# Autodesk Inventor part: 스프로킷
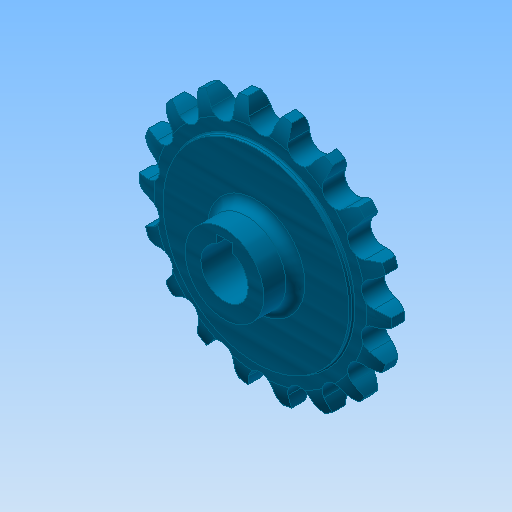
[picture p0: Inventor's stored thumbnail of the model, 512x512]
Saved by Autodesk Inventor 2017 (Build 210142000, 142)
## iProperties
Created: 2016-03
Part Number: 스프로킷
Material: 강철, 탄소
Document SubType Name: Modeling
Designer: mduedu
Density: 7.87 g/cm^3
Mass: 301.818 g
Surface Area: 124.882 cm^2
Volume: 38.3505 cm^3
Appearance: 하늘색 중간
Author: mduedu
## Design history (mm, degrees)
sketch "스케치1"
  geometry: L1 (0, 5)-(29.5, 5); L2 (29.5, 5)-(29.5, 4.1); L3 (30, 3.6)-(33.625, 3.6); L4 (40, 2)-(40, 0); L5 (40, 0)-(0, 0); L6 (0, 0)-(0, 5); L7 (0, -5)-(29.5, -5); L8 (29.5, -5)-(29.5, -4.1); L9 (30, -3.6)-(33.625, -3.6); L10 (40, -2)-(40, 0); L11 (0, 0)-(0, -5); A1 r 13.5 centre (33.625, -9.9) between (40, 2) and (33.625, 3.6); A2 r 13.5 centre (33.625, 9.9) between (33.625, -3.6) and (40, -2); A3 r 0.5 centre (30, 4.1) between (29.5, 4.1) and (30, 3.6); A4 r 0.5 centre (30, -4.1) between (30, -3.6) and (29.5, -4.1); 2 further points
  constraints: 22 end point, 8 point on circle, 6 symmetric about line, 5 tangent, 4 centre point, 4 parallel, 4 point on line, 1 equal radius, 1 horizontal, 1 perpendicular, 1 other
  dimensions: "d0" = 80 diameter of L4 L6; "d2" = 59 diameter of L2 L6; "d3" = 1.6 vertical distance of L4.start L3.end; "d4" = 3.6 distance from line of L4.end L3; "d5" = 5 distance between parallel lines of L5 L1; "d6" = 13.5 radius of A1; "d15" = 0.5 radius of A3
revolve "회전1" sketch "스케치1" stored, may be unused: angle "d7" = 90 deg
sketch "스케치2" dims "d8" = 65.2, "d11" = 80
  geometry: L1 (0, 0)-(0, 32.6); A1 r 36.57 centre (0, 0) between (-16.231, 32.771) and (0, 36.57); A2 r 3.97 centre (0, 36.57) between (-3.866, 35.665) and (0, 32.6); A3 r 12.7 centre (-16.231, 32.771) between (-3.866, 35.665) and (-5.534, 39.615); A4 r 12.7 centre (16.231, 32.771) between (5.534, 39.615) and (3.866, 35.665); A5 r 3.97 centre (0, 36.57) between (0, 32.6) and (3.866, 35.665); A6 r 40 centre (0, 0) between (5.534, 39.615) and (-5.534, 39.615); 2 further points
  constraints: 12 point on circle, 6 centre point, 4 coincident, 3 symmetric about line, 2 end point, 1 point on line, 1 tangent, 1 vertical, 1 vertical alignment, 7 other
  dimensions: "d10" = 73.14 diameter of A1; "d12" = 12.7 radius of A3
extrude "돌출1" cut sketch "스케치2" stored distance "d13" = 10; taper "d14" = 0 deg
sketch "스케치3"
  geometry: C1 r 12.5 at (0, 0); 1 further point
  constraints: 1 centre point, 1 coincident
  dimensions: "d19" = 25 diameter of C1
extrude "돌출2" join sketch "스케치3" distance "d20" = 10; taper "d21" = 0 deg
fillet "모깎기1" dims "d22" = 3
sketch "스케치4"
  geometry: L1 (-2.5, 0)-(2.5, 0); L2 (2.5, 0)-(2.5, 9.8); L3 (2.5, 9.8)-(-2.5, 9.8); L4 (-2.5, 9.8)-(-2.5, 0); C1 r 7.5 at (0, 0); 2 further points
  constraints: 8 end point, 2 coincident, 2 parallel, 1 centre point, 1 horizontal, 1 midpoint, 1 perpendicular
  dimensions: "d23" = 15 diameter of C1; "d25" = 5 distance of L2.end L3.end; "d26" = 9.8 distance of L1.end L2.end
extrude "돌출3" cut sketch "스케치4" stored distance "d27" = 8; taper "d28" = 0 deg
node "솔리드1"
pattern_circular "원형 패턴1" dims angle "d17" = 360 deg
